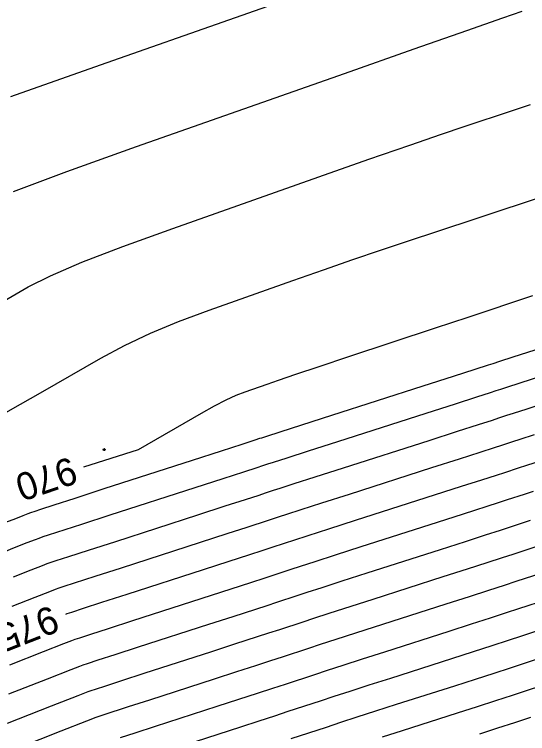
# Model space of a CAD drawing. Extents: x 2175772 to 2185556, y 721391 to 722853.
# Drawn here: x 2178849.6 to 2178902, y 721896.5 to 721969.8 of the extents above; entities that cross this region are included whole.
import ezdxf

# ---------------------------------------------------------------- set-up
doc = ezdxf.new("R2010")
doc.units = 0
for name, color, linetype in [('DT_X_Contour_Major', 7, 'Continuous'), ('DT_X_Contour_Minor', 7, 'Continuous'), ('RD_X_Misc_Items', 7, 'Continuous')]:
    doc.layers.add(name, color=color, linetype=linetype)

msp = doc.modelspace()

# ---------------------------------------------------------------- linework, layer by layer
at = {"layer": 'DT_X_Contour_Major'}
for points in [[(2178856.709, 721923.67), (2178862.269, 721925.467), (2178868.729, 721929.168), (2178870.045, 721929.899), (2178871.225, 721930.505), (2178872.269, 721930.987), (2178873.177, 721931.345), (2178875.417, 721932.134), (2178876.568, 721932.53), (2178878.34, 721933.128), (2178880.734, 721933.927), (2178883.749, 721934.928), (2178892.619, 721937.865), (2178895.939, 721938.964), (2178902.542, 721941.15)], [(2178854.872, 721908.665), (2178855.006, 721908.711), (2178855.493, 721908.871), (2178856.675, 721909.255), (2178858.552, 721909.862), (2178861.125, 721910.694), (2178868.913, 721913.21), (2178871.536, 721914.058), (2178873.564, 721914.714), (2178874.997, 721915.179), (2178875.834, 721915.452), (2178877.275, 721915.925), (2178878.128, 721916.202), (2178879.604, 721916.678), (2178881.704, 721917.353), (2178884.428, 721918.227), (2178895.248, 721921.696), (2178897.346, 721922.371), (2178898.818, 721922.845), (2178899.664, 721923.12), (2178901.087, 721923.587), (2178901.934, 721923.862), (2178903.409, 721924.338)], [(2178860.443, 721896.069), (2178861.959, 721896.56), (2178864.036, 721897.232), (2178870.326, 721899.264), (2178872.53, 721899.976), (2178874.425, 721900.591), (2178876.01, 721901.107), (2178877.287, 721901.524), (2178880.278, 721902.507), (2178881.567, 721902.927), (2178883.189, 721903.453), (2178885.145, 721904.083), (2178887.434, 721904.818), (2178893.983, 721906.918), (2178896.272, 721907.653), (2178898.224, 721908.282), (2178899.84, 721908.805), (2178901.12, 721909.223), (2178904.086, 721910.197)]]:
    msp.add_lwpolyline(points, dxfattribs=at)
at = {"layer": 'DT_X_Contour_Minor'}
for points in [[(2178849.267, 721961.456), (2178858.401, 721964.692), (2178885.951, 721974.391)], [(2178849.522, 721951.789), (2178854.973, 721953.813), (2178862.095, 721956.355), (2178883.318, 721963.826), (2178890.419, 721966.324), (2178895.806, 721968.212), (2178899.479, 721969.49), (2178901.437, 721970.159)], [(2178846.261, 721939.298), (2178851.036, 721942.034), (2178853.301, 721943.177), (2178856.515, 721944.556), (2178860.678, 721946.17), (2178865.789, 721948.018), (2178880.684, 721953.262), (2178885.802, 721955.059), (2178889.984, 721956.517), (2178893.231, 721957.636), (2178895.541, 721958.416), (2178900.456, 721960.043), (2178902.295, 721960.652)], [(2178848.724, 721929.232), (2178850.226, 721930.074), (2178852.268, 721931.238), (2178858.433, 721934.771), (2178860.858, 721936.071), (2178863.508, 721937.323), (2178866.383, 721938.527), (2178869.483, 721939.682), (2178878.051, 721942.698), (2178881.185, 721943.795), (2178884.162, 721944.822), (2178886.982, 721945.781), (2178889.645, 721946.672), (2178896.538, 721948.954), (2178899.117, 721949.808), (2178901.688, 721950.659), (2178904.248, 721951.507)], [(2178848.747, 721918.035), (2178849.747, 721918.428), (2178850.508, 721918.725), (2178851.028, 721918.925), (2178851.308, 721919.029), (2178851.736, 721919.176), (2178852.297, 721919.36), (2178853.661, 721919.803), (2178855.827, 721920.504), (2178858.796, 721921.464), (2178867.782, 721924.368), (2178870.741, 721925.323), (2178872.875, 721926.013), (2178874.186, 721926.437), (2178874.673, 721926.595), (2178874.873, 721926.66), (2178875.376, 721926.822), (2178876.736, 721927.258), (2178878.952, 721927.969), (2178882.024, 721928.954), (2178891.357, 721931.947), (2178894.429, 721932.932), (2178896.643, 721933.642), (2178898, 721934.077), (2178898.499, 721934.237), (2178899.187, 721934.46), (2178900.545, 721934.896), (2178902.762, 721935.607)], [(2178847.882, 721914.756), (2178849.629, 721915.442), (2178850.921, 721915.948), (2178851.758, 721916.273), (2178852.14, 721916.417), (2178852.553, 721916.56), (2178853.096, 721916.738), (2178856.508, 721917.844), (2178859.378, 721918.772), (2178868.065, 721921.578), (2178870.939, 721922.507), (2178873.047, 721923.188), (2178874.388, 721923.622), (2178874.963, 721923.809), (2178875.474, 721923.977), (2178876.064, 721924.167), (2178877.453, 721924.613), (2178879.64, 721925.315), (2178882.625, 721926.272), (2178891.649, 721929.166), (2178894.634, 721930.123), (2178896.819, 721930.824), (2178898.204, 721931.269), (2178898.79, 721931.458), (2178899.287, 721931.621), (2178899.874, 721931.811), (2178901.261, 721932.256), (2178903.449, 721932.958)], [(2178849.511, 721912.457), (2178851.334, 721913.172), (2178852.488, 721913.622), (2178852.972, 721913.806), (2178853.371, 721913.943), (2178853.895, 721914.116), (2178855.168, 721914.529), (2178857.19, 721915.183), (2178859.96, 721916.079), (2178868.348, 721918.789), (2178871.138, 721919.691), (2178873.219, 721920.364), (2178874.591, 721920.808), (2178875.254, 721921.023), (2178876.074, 721921.293), (2178876.752, 721921.512), (2178878.17, 721921.968), (2178880.328, 721922.661), (2178883.226, 721923.591), (2178891.941, 721926.385), (2178894.838, 721927.314), (2178896.994, 721928.006), (2178898.409, 721928.461), (2178899.081, 721928.679), (2178899.887, 721928.943), (2178900.561, 721929.161), (2178901.977, 721929.617), (2178904.136, 721930.31)], [(2178849.392, 721909.471), (2178851.747, 721910.395), (2178853.218, 721910.97), (2178853.804, 721911.195), (2178854.189, 721911.327), (2178854.694, 721911.493), (2178857.871, 721912.523), (2178860.543, 721913.387), (2178868.63, 721916), (2178871.337, 721916.874), (2178873.392, 721917.539), (2178875.544, 721918.238), (2178876.675, 721918.609), (2178877.44, 721918.857), (2178878.887, 721919.323), (2178881.016, 721920.007), (2178883.827, 721920.909), (2178892.233, 721923.604), (2178895.043, 721924.505), (2178897.17, 721925.188), (2178898.613, 721925.653), (2178899.373, 721925.899), (2178900.487, 721926.265), (2178901.247, 721926.512), (2178902.693, 721926.977)], [(2178849.156, 721903.499), (2178852.574, 721904.842), (2178854.678, 721905.667), (2178855.468, 721905.972), (2178855.824, 721906.095), (2178856.292, 721906.249), (2178857.428, 721906.618), (2178859.234, 721907.202), (2178861.707, 721908.002), (2178871.735, 721911.242), (2178873.736, 721911.89), (2178875.199, 721912.365), (2178876.125, 721912.667), (2178877.876, 721913.242), (2178878.815, 721913.547), (2178880.321, 721914.033), (2178882.392, 721914.699), (2178885.029, 721915.545), (2178892.816, 721918.042), (2178895.453, 721918.888), (2178899.022, 721920.037), (2178899.955, 721920.341), (2178901.687, 721920.909), (2178902.621, 721921.213)], [(2178849.037, 721900.513), (2178852.987, 721902.066), (2178855.408, 721903.015), (2178856.3, 721903.361), (2178856.642, 721903.479), (2178857.091, 721903.626), (2178858.182, 721903.98), (2178859.915, 721904.541), (2178862.29, 721905.309), (2178869.478, 721907.632), (2178871.933, 721908.425), (2178875.402, 721909.55), (2178876.415, 721909.881), (2178878.476, 721910.558), (2178879.503, 721910.892), (2178881.038, 721911.388), (2178883.08, 721912.045), (2178885.63, 721912.863), (2178893.108, 721915.261), (2178895.657, 721916.079), (2178897.697, 721916.735), (2178899.226, 721917.229), (2178900.246, 721917.561), (2178902.287, 721918.231)], [(2178848.919, 721897.527), (2178853.4, 721899.289), (2178856.138, 721900.363), (2178857.132, 721900.75), (2178857.46, 721900.862), (2178857.89, 721901.004), (2178858.935, 721901.343), (2178860.596, 721901.881), (2178862.872, 721902.617), (2178869.761, 721904.842), (2178872.132, 721905.609), (2178875.605, 721906.736), (2178876.706, 721907.096), (2178879.077, 721907.874), (2178880.191, 721908.237), (2178881.755, 721908.743), (2178886.232, 721910.182), (2178893.4, 721912.48), (2178895.862, 721913.27), (2178897.872, 721913.917), (2178899.431, 721914.421), (2178900.538, 721914.782), (2178902.886, 721915.553)], [(2178850.097, 721895.051), (2178854.389, 721896.739), (2178857.012, 721897.768), (2178857.964, 721898.138), (2178858.277, 721898.246), (2178858.689, 721898.382), (2178861.277, 721899.22), (2178863.454, 721899.924), (2178870.043, 721902.053), (2178872.331, 721902.793), (2178874.253, 721903.416), (2178875.808, 721903.921), (2178876.996, 721904.31), (2178879.678, 721905.19), (2178880.879, 721905.582), (2178882.472, 721906.098), (2178884.457, 721906.737), (2178893.692, 721909.699), (2178896.067, 721910.461), (2178898.048, 721911.099), (2178899.635, 721911.613), (2178900.829, 721912.003), (2178903.486, 721912.875)], [(2178864.619, 721894.539), (2178872.729, 721897.16), (2178874.597, 721897.766), (2178876.213, 721898.292), (2178877.577, 721898.739), (2178880.879, 721899.823), (2178882.255, 721900.272), (2178883.906, 721900.808), (2178885.833, 721901.429), (2178888.035, 721902.136), (2178894.275, 721904.137), (2178896.476, 721904.844), (2178898.399, 721905.464), (2178900.044, 721905.997), (2178901.411, 721906.444), (2178904.686, 721907.519)], [(2178877.868, 721895.953), (2178881.479, 721897.139), (2178882.942, 721897.617), (2178884.623, 721898.163), (2178886.521, 721898.775), (2178888.636, 721899.455), (2178894.567, 721901.356), (2178896.681, 721902.035), (2178898.575, 721902.646), (2178900.249, 721903.189), (2178901.703, 721903.664), (2178905.286, 721904.841)], [(2178887.209, 721896.121), (2178889.237, 721896.773), (2178894.859, 721898.575), (2178896.886, 721899.226), (2178898.751, 721899.828), (2178900.453, 721900.381), (2178901.994, 721900.885), (2178905.886, 721902.163)], [(2178902.285, 721898.106), (2178900.658, 721897.573), (2178898.926, 721897.011), (2178897.09, 721896.418)]]:
    msp.add_lwpolyline(points, dxfattribs=at)
at = {"layer": 'RD_X_Misc_Items'}
msp.add_line((2178858.785, 721925.396), (2178858.785, 721925.42), dxfattribs=at)
for centre, radius in [((2178858.785, 721925.434), 0.1), ((2178858.785, 721925.363), 0.00852)]:
    msp.add_circle(centre, radius, dxfattribs=at)
for centre, radius, start, end in [((2178858.782, 721925.475), 0.0377, 88.32401, 152.53853), ((2178858.784, 721925.478), 0.0344, 291.93294, 92.45835), ((2178858.814, 721925.422), 0.0294, 125.46179, 184.08291)]:
    msp.add_arc(centre, radius, start, end, dxfattribs=at)

# ---------------------------------------------------------------- texts
at = {"layer": 'DT_X_Contour_Major'}
for s, rotation, p in [('970', 198.66915, (2178855.397, 721924.763)), ('975', 201.33606, (2178853.414, 721909.609))]:
    msp.add_text(s, height=2.8, rotation=rotation, dxfattribs=at).set_placement(p)

doc.saveas('drawing.dxf')
